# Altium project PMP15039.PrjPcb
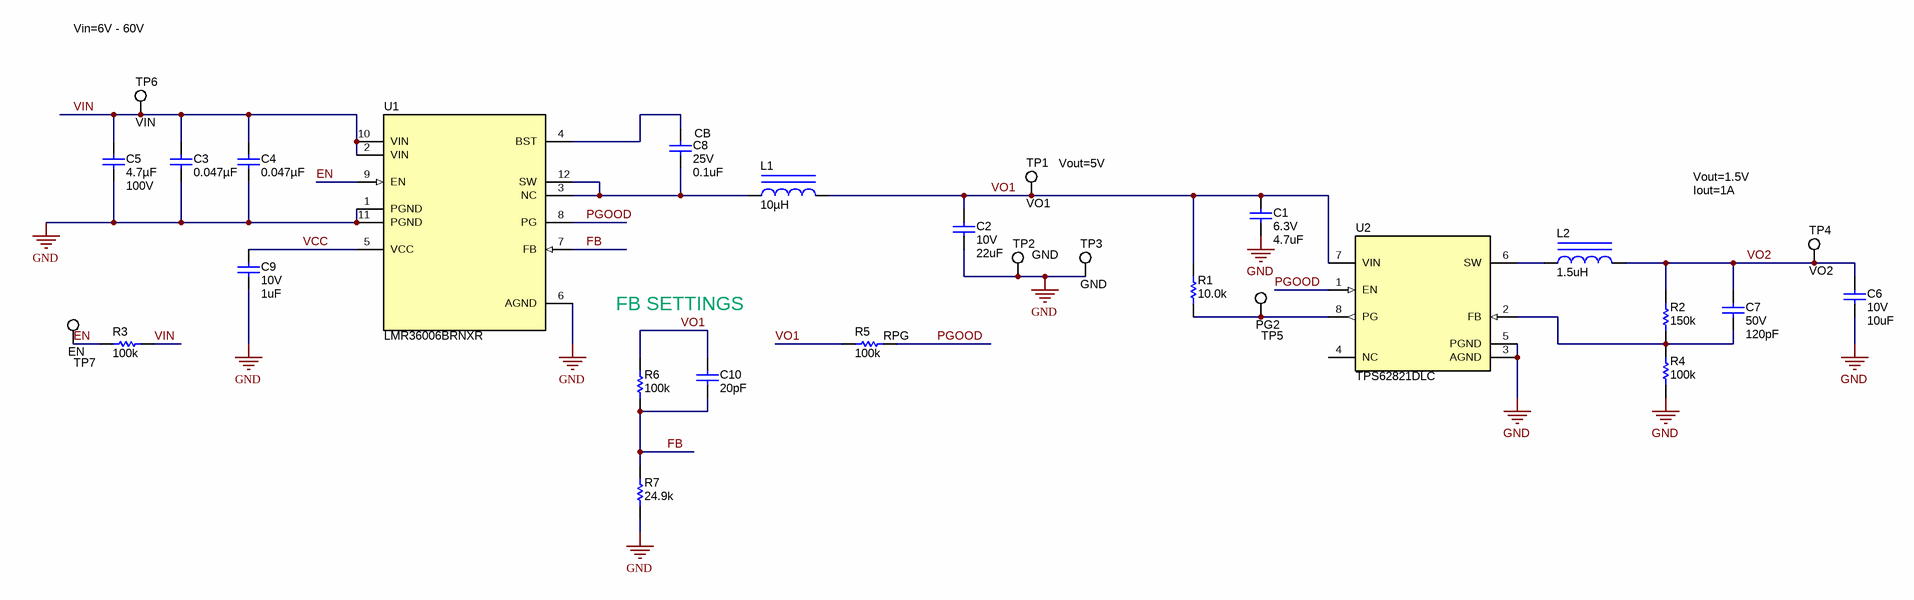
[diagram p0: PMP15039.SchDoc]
TID: PMP15039; TechSupport: http://www.ti.com/support; SCH_Rev: E1; PRJ_Title: Two-Stage Power Supply for Field Transmitters Reference Design; PRJ_Number: PMP15039; PRJ_Engineer: Katelyn Wiggenhorn; PRJ_Customer: Public Release; PCB_Rev: E1; PCB_Layout: Katelyn Wiggenhorn; CopyrightYear: 2017
2 sheets, 34 parts. Net scope: global (net labels, ports and power ports of the same name join across sheets).
Board file: PMP15039.PcbDoc
Sheets:
  PMP15039.SchDoc
  PMP15039_Hardware.SchDoc

## Sheet PMP15039.SchDoc
size 431 x 279 mm; Date: Not shown in title block; ApprovedBy: Not shown in title block; CheckedBy: Not shown in title block; Author: Not shown in title block; CompanyName: Not shown in title block; Engineer: Not shown in title block; Organization: Not shown in title block; Address1: Not shown in title block; Address2: Not shown in title block; Address3: Not shown in title block; Address4: Not shown in title block; DocumentNumber: 1; Revision: Use project parameter SCH_Rev; SheetNumber: 2; SheetTotal: 3; PageSetup: Record=PageOptions¦CenterHorizontal=True¦CenterVertical=True¦PrintScale=1.00¦XCorrection=1.00¦YCorrection=1.00¦PrintKind=0¦BorderSize=5000000¦LeftOffset=0¦BottomOffset=0¦Orientation=2¦PaperLength=1000¦PaperWidth=1000¦Scale=100¦PaperSource=15¦PrintQuality=600¦MediaType=1¦DitherType=10¦PaperKind=Letter¦PrintScaleMode=1

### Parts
C1  VDC_V: 6.3V  ValueDisplayed: 4.7uF  [0603]  (hidden comment: JMK107BB7475MA-T)
C2  VDC_V: 10V  ValueDisplayed: 22uF  [0805_HV]  (hidden comment: GRM21BZ71A226ME15L)
C3  ValueDisplayed: 0.047µF  [0603L]  (hidden comment: CIN3)
C4  ValueDisplayed: 0.047µF  [0603L]  (hidden comment: CIN1)
C5  ValueDisplayed: 4.7µF  Value2: 100V  [1210_220L]  (hidden comment: CIN2)
C6  VDC_V: 10V  ValueDisplayed: 10uF  [0805L]  (hidden comment: GRM21BR71A106ME51L)
C7  VDC_V: 50V  ValueDisplayed: 120pF  [0402]  (hidden comment: GRM1555C1H121FA01D)
C8  CB  VDC_V: 25V  ValueDisplayed: 0.1uF  [0402L]
C9  VDC_V: 10V  ValueDisplayed: 1uF  [0402]  (hidden comment: C1005X7S1A105K050BC)
C10  ValueDisplayed: 20pF  [0402L]  (hidden comment: CFF)
L1  ValueDisplayed: 10µH  [WE-MAPI_4030]  (hidden comment: 74438357100)
L2  ValueDisplayed: 1.5uH  [XFL3012]  (hidden comment: XFL3012-152MEB)
R1  ValueDisplayed: 10.0k  [0402L]  (hidden comment: RPG2)
R2  ValueDisplayed: 150k  [0402]  (hidden comment: ERJ-2RKF1503X)
R3  ValueDisplayed: 100k  [0402L]  (hidden comment: CRCW0402100KFKED)
R4  ValueDisplayed: 100k  [0402L]  (hidden comment: RFBB2)
R5  RPG  ValueDisplayed: 100k  [0402L]
R6  ValueDisplayed: 100k  [0402L]  (hidden comment: CRCW0402100KFKED)
R7  ValueDisplayed: 24.9k  [0402L]  (hidden comment: CRCW040224K9FKED)
TP1  VO1  [Testpoint_Keystone_Miniature]
TP2  GND  [Testpoint_Keystone_Miniature]
TP3  GND  [Testpoint_Keystone_Miniature]
TP4  VO2  [Testpoint_Keystone_Miniature]
TP5  PG2  [Testpoint_Keystone_Miniature]
TP6  VIN  [Testpoint_Keystone_Miniature]
TP7  EN  [Testpoint_Keystone_Miniature]
U1  LMR36006BRNXR  [RNX0012B]
U2  TPS62821DLC  [DLC0008A]

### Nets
GND: C1.2 C2.2 C3.2 C4.2 C5.1 C6.2 C9.2 R4.1 R7.1 TP2.1 TP3.1 U1.1(PGND) U1.6(AGND) U1.11(PGND) U2.3(AGND) U2.5(PGND)
EN: R3.2 TP7.1 U1.9(EN)
FB: C10.2 R6.1 R7.2 U1.7(FB)
PGOOD: R5.1 U1.8(PG) U2.1(EN)
VCC: C9.1 U1.5(VCC)
VIN: C3.1 C4.1 C5.2 R3.1 TP6.1 U1.2(VIN) U1.10(VIN)
VO1: C1.1 C2.1 C10.1 L1.2 R1.2 R5.2 R6.2 TP1.1 U2.7(VIN)
VO2: C6.1 C7.1 L2.2 R2.2 TP4.1
NetC7_2: C7.2 R2.1 R4.2 U2.2(FB)
NetC8_1: C8.1 U1.4(BST)
NetC8_2: C8.2 L1.1 U1.3(NC) U1.12(SW)
NetL2_1: L2.1 U2.6(SW)
NetR1_1: R1.1 TP5.1 U2.8(PG)

Not connected (* = marked no-connect by the designer): U2 4(NC)

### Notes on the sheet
- Vin=6V - 60V
- (near TP1) Vout=5V
- (near TP4) Vout=1.5V
  Iout=1A
- FB SETTINGS

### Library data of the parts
C1 = CMP-0007503-4: CAP, CERM, 4.7 uF, 6.3 V, +/- 10%, X7R, 0603; Manufacturer: Taiyo Yuden; TaMin_C: -55°C; Polarized: N; SizeAreaWB_mm2: 4.68; Value1: Unknown; U/M: EA; Value: 4.7uF; TaMax_C: 125°C; SizeZ_mm: 1; SizeX_mm: 1.6; SizeY_mm: 0.8; SizeArea_mm2: 1.28; CompType: Capacitor; Cap_F: 4.7µF; AEC Category: Q200
C2 = CMP-0008377-2: CAP, CERM, 22 uF, 10 V, +/- 20%, X7R, 0805; Manufacturer: MuRata; SizeY_mm: 1.25; Cap_Case: 0805; SizeArea_mm2: 2.5; CompType: Capacitor; AEC Qualified: N; Cap_F: 22µF; AEC Category: Q200; TaMin_C: -55°C; SizeAreaWB_mm2: 6.75; Value1: Unknown; U/M: EA; Value: 22uF; TaMax_C: 125°C; SizeZ_mm: 1.45; SizeX_mm: 2
C3 C4 = CGA3E3X7S2A473K080AB: CAP, CERM, 0.047 µF, 100 V,+/- 10%, X7S, AEC-Q200 Grade 1, 0603; Manufacturer: TDK; Polarized: N; CompType: Capacitor; Value: 0.047uF; U/M: EA; Cap_F: 0.000000047; Tolerance_%: 10; ESR_ohm: 0.089796; Value1: 0.089796 ohm; VDC_V: 100; Value2: 100V; IRMS_A: 0.567484; TaMin_C: -55; TaMax_C: 125; Cap_Case: 0603; SizeArea_mm2: 1.28; SizeAreaWB_mm2: 4.68; SizeX_mm: 1.6; SizeY_mm: 0.8; SizeZ_mm: 1; AEC Category: Q200; AEC Qualified: Y
C5 = CGA6M3X7S2A475K200AB: CAP, CERM, 4.7 µF, 100 V, +/- 10%, X7S, AEC-Q200 Grade 1, 1210; Manufacturer: TDK; Polarized: N; CompType: Capacitor; Value: 4.7uF; U/M: EA; Cap_F: 0.0000047; Tolerance_%: 10; ESR_ohm: 0.004236; Value1: 0.004236 ohm; VDC_V: 100; IRMS_A: 3.57337; TaMin_C: -55; TaMax_C: 125; Cap_Case: 1210_220; SizeArea_mm2: 8; SizeAreaWB_mm2: 14.7; SizeX_mm: 3.2; SizeY_mm: 2.5; SizeZ_mm: 2.2; AEC Category: Q200; AEC Qualified: Y; AEC Grade: 1
C6 = CMP-0008316-2: CAP, CERM, 10 uF, 10 V, +/- 20%, X7R, 0805; Manufacturer: MuRata; TaMin_C: -55°C; Polarized: N; SizeAreaWB_mm2: 6.75; Value1: Unknown; U/M: EA; Value: 10uF; TaMax_C: 125°C; SizeZ_mm: 1.45; SizeX_mm: 2; SizeY_mm: 1.25; Cap_Case: 0805; SizeArea_mm2: 2.5; CompType: Capacitor; Cap_F: 10µF; AEC Category: Q200
C7 = CMP-0006416-2: CAP, CERM, 120 pF, 50 V, +/- 1%, C0G/NP0, 0402; Manufacturer: MuRata; TaMin_C: -55°C; Polarized: N; SizeAreaWB_mm2: 3; Value1: Unknown; U/M: EA; Value: 120pF; TaMax_C: 125°C; SizeZ_mm: 0.6; SizeX_mm: 1; SizeY_mm: 0.5; CompType: Capacitor; AEC Category: Q200
C8 = CMP-0006659-2: CAP, CERM, 0.1 uF, 25 V, +/- 10%, X7R, 0402; Manufacturer: MuRata; PartNumber: GRM155R71E104KE14D; TaMin_C: -55°C; Polarized: N; SizeAreaWB_mm2: 3; Value1: Unknown; U/M: EA; Value: 0.1uF; TaMax_C: 125°C; SizeZ_mm: 0.6; SizeX_mm: 1; SizeY_mm: 0.5; Cap_Case: 0402; CompType: Capacitor; Cap_F: 100nF; AEC Category: Q200
C9 = CMP-0006300-2: CAP, CERM, 1 uF, 10 V, +/- 10%, X7S, 0402; Manufacturer: TDK; TaMin_C: -55°C; ESR_ohm: 0.011416; Polarized: N; SizeAreaWB_mm2: 3; Value1: 0.011416 ohm; U/M: EA; Value: 1uF; TaMax_C: 125°C; SizeZ_mm: 0.6; SizeX_mm: 1; SizeY_mm: 0.5; CompType: Capacitor; Cap_F: 1µF; IRMS_A: 1.483A; AEC Category: Q200
C10 = GRM1555C1E200JA01D: CAP, CERM, 20 pF, 25 V,+/- 5%, C0G/NP0, 0402; Manufacturer: MuRata; Polarized: N; CompType: Capacitor; Value: 20pF; U/M: EA; Cap_F: 0.00000000002; Tolerance_%: 5; VDC_V: 25; Value2: 25V; TaMin_C: -55; TaMax_C: 125; Cap_Case: 0402; SizeArea_mm2: 0.5; SizeAreaWB_mm2: 3; SizeX_mm: 1; SizeZ_mm: 0.6; AEC Category: Q200
L1 = CMP-0081728-1: Inductor, Shielded, Metal Composite, 10 µH, 2.7 A, 0.11 ohm, SMD; Manufacturer: Wurth Elektronik; SizeAreaWB_mm2: 26.01; Irms: 2.7A @ 40C rise; SizeArea_mm2: 16.81; AEC Qualified: N; AEC Category: Q200; Value: 10uH; SizeZ_mm: 3.1; Imax_A: 2.7A; SizeY_mm: 4.1; Isat: 4.6A @ 20% inductance drop; DCR_ohm: 0.11
L2 = CMP-0061135-1: Inductor, Shielded, Composite, 1.5 uH, 2.2 A, 0.06 ohm, SMD; Manufacturer: Coilcraft; Isat: 2.2A @ 30% inductance drop; Irms: 2.2A @ 40C rise; Green_Lifecycle: Not Set; SizeAreaWB_mm2: 16; DCR_ohm: 0.06; Green_REACh: Incomplete; Value: 1.5uH; Imax_A: 2.2A; SizeZ_mm: 1.2; SizeX_mm: 3; SizeArea_mm2: 9; Ind_H: 1.5µH; AEC Category: Q200
R1 = CMP-0025958-2: RES, 10.0 k, 1%, 0.063 W, 0402; Manufacturer: Vishay-Dale; PartNumber: CRCW040210K0FKED; Power_W: 63mW; TempCo: 100 ppm/C; Value_Code: 10k0; U/M: EA; Value: 10.0k; EIA_Code: E96; Res_ohm: 10k; SizeX_mm: 1; SizeY_mm: 0.5; SizeZ_mm: 0.6; Value2: 0.063W; CompType: Resistor; VDC_V: 50V; AEC Category: Q200
R2 = CMP-0026669-1: RES, 150 k, 1%, 0.1 W, AEC-Q200 Grade 0, 0402; Manufacturer: Panasonic; Power_W: 100mW; TempCo: 100 ppm/C; U/M: EA; Value: 150k; EIA_Code: E96; SizeX_mm: 1; SizeY_mm: 0.5; SizeZ_mm: 0.6; Value2: 0.1W; CompType: Resistor; AEC Qualified: Y; VDC_V: 50V; AEC Grade: 0; AEC Category: Q200
R3 R5 R6 = CRCW0402100KFKED: RES, 100 k, 1%, 0.063 W, 0402; Manufacturer: Vishay-Dale; CompType: Resistor; Value: 100k; Res_ohm: 100000; Tolerance_%: 1; Power_W: 0.063; Value2: 0.063W; VDC_V: 50; TempCo: 100 ppm/C; SizeArea_mm2: 0.5; SizeZ_mm: 0.6; EIA_Code: E96; U/M: EA; AEC Category: Q200; Green_Lifecycle: Active; Green_REACh: Passed
R4 = CMP-0025950-2: RES, 100 k, 1%, 0.063 W, 0402; Manufacturer: Vishay-Dale; PartNumber: CRCW0402100KFKED; Power_W: 63mW; TempCo: 100 ppm/C; U/M: EA; Value: 100k; EIA_Code: E96; SizeX_mm: 1; SizeY_mm: 0.5; SizeZ_mm: 0.6; Value2: 0.063W; CompType: Resistor; VDC_V: 50V; AEC Category: Q200
R7 = CMP-0026196-1: RES, 24.9 k, 1%, 0.063 W, 0402; Manufacturer: Vishay-Dale; Power_W: 63mW; TempCo: 100 ppm/C; Value_Code: 24k9; U/M: EA; Value: 24.9k; EIA_Code: E96; SizeX_mm: 1; SizeY_mm: 0.5; SizeZ_mm: 0.6; Value2: 0.063W; CompType: Resistor; VDC_V: 50V; AEC Category: Q200
TP1-TP7 = CMP-0055152-1: Test Point, Miniature, SMT; Manufacturer: Keystone; PartNumber: 5015; CNHeader: FALSE; Green_Lifecycle: Active; Green_REACh: Passed; CT: TRUE
U1 = CMP-0077274-3: 65-V 0.6-A Synchronous Step-Down Converter, RNX0012B (VQFN-HR-12); Alternate PartNumber: LMR36006BRNXT; Alternate Manufacturer: Texas Instruments; SizeAreaWB_mm2: 12.0; SizeZ_mm: 1.0; SizeX_mm: 2.0; SizeY_mm: 3.0; SizeArea_mm2: 6.0; CompType: IC; AEC Qualified: N; AEC Category: Q200
U2 = CMP-0065148-2: 2.5-V to 5.5-V, 1-, 2-, 3-A Step-Down Converter with DCS-Control, DLC0008A (SON-HR-8); Manufacturer: Texas Instruments; SizeX_mm: 1.5; SizeY_mm: 2.0; CompType: IC; SizeZ_mm: 1.0; SizeArea_mm2: 3.0; SizeAreaWB_mm2: 7.5; U/M: EA

## Sheet PMP15039_Hardware.SchDoc
size 431 x 279 mm; Date: Not shown in title block; ApprovedBy: Not shown in title block; CheckedBy: Not shown in title block; Author: Not shown in title block; CompanyName: Not shown in title block; Engineer: Not shown in title block; Organization: Not shown in title block; Address1: Not shown in title block; Address2: Not shown in title block; Address3: Not shown in title block; Address4: Not shown in title block; DocumentNumber: 1; Revision: Use project parameter SCH_Rev; SheetNumber: 3; SheetTotal: 3; PageSetup: Record=PageOptions¦CenterHorizontal=True¦CenterVertical=True¦PrintScale=1.00¦XCorrection=1.00¦YCorrection=1.00¦PrintKind=0¦BorderSize=5000000¦LeftOffset=0¦BottomOffset=0¦Orientation=2¦PaperLength=1000¦PaperWidth=1000¦Scale=100¦PaperSource=15¦PrintQuality=600¦MediaType=1¦DitherType=10¦PaperKind=Letter¦PrintScaleMode=1
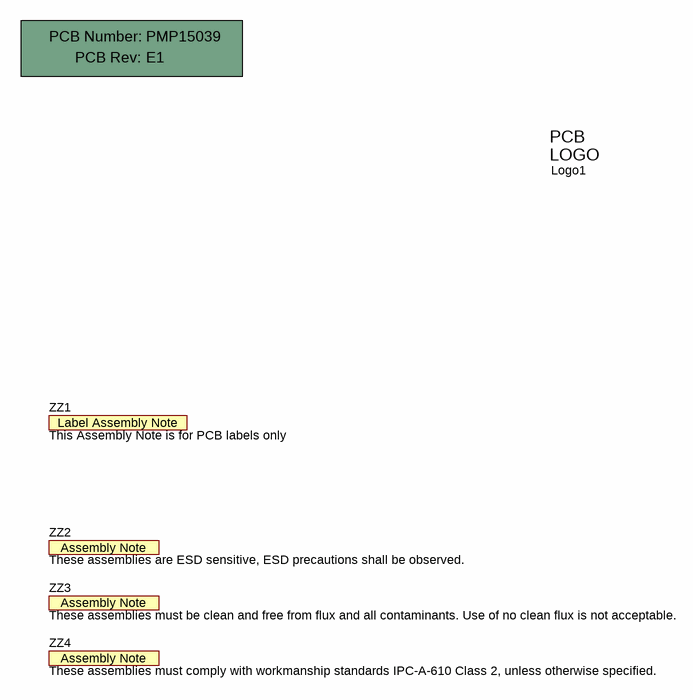
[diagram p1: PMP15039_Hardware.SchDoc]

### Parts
!PCB  Printed Circuit Board  (value not drawn)  (mechanical)
Logo1  Texas Instruments  [TI_Symbol_Overlay_Small]  (value not drawn)  (no BOM)
ZZ1  This Assembly Note is for PCB labels only  [AssemblyNoteLabel]  (no BOM)
ZZ2  These assemblies are ESD sensitive, ESD precautions shall be observed.  [AssemblyNote]  (no BOM)
ZZ3  These assemblies must be clean and free from flux and all contaminants. Use of no clean flux is not acceptable.  [AssemblyNote]  (no BOM)
ZZ4  These assemblies must comply with workmanship standards IPC-A-610 Class 2, unless otherwise specified.  [AssemblyNote]  (no BOM)

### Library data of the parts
!PCB = CMP-0003618-2: Manufacturer: Any; PartNumber: PMP15039
Logo1 = TI_Logo: Texas Instrument Corporate Signature; SymbolCreator: a0412235
ZZ1 = CMP-0003616-3
ZZ2 = CMP-0077236-1
ZZ3 = CMP-0077237-1
ZZ4 = CMP-0077238-1

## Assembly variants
001: all parts fitted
